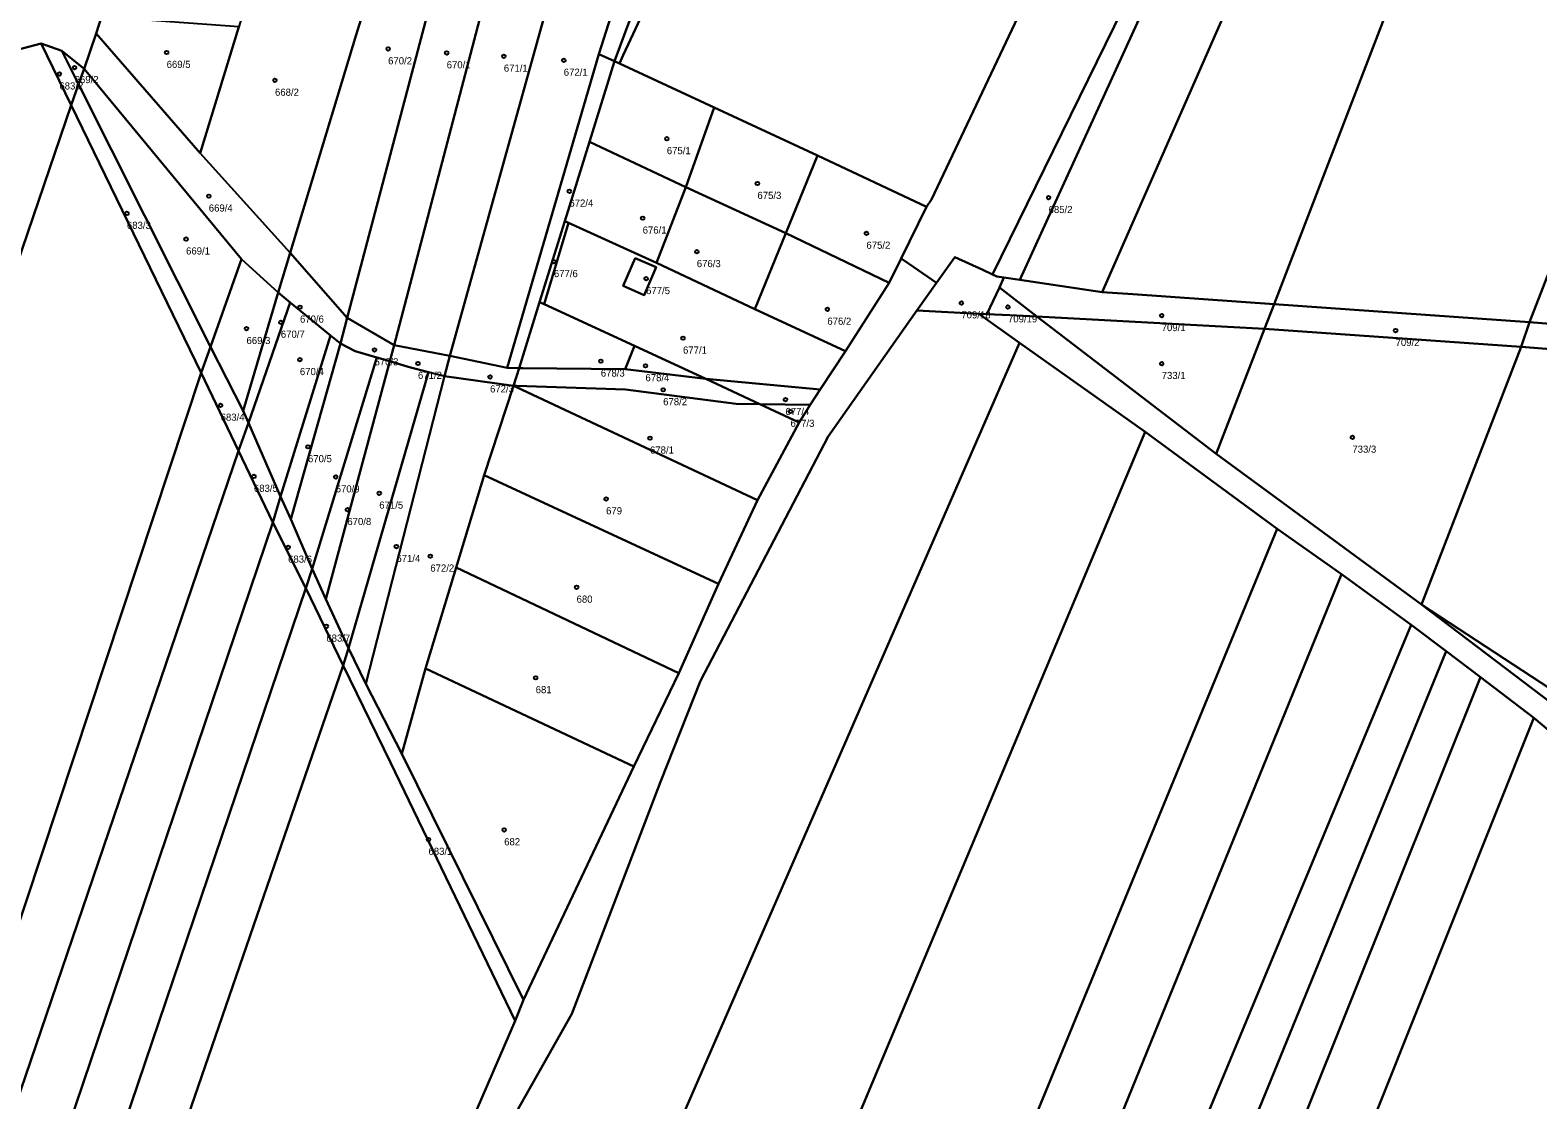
# Model space of a CAD drawing. Extents: x -587171 to -555306, y -1167727 to -1074732.
# Drawn here: x -585851.6 to -585640.5, y -1166041.5 to -1165891.7 of the extents above; entities that cross this region are included whole.
import ezdxf

# ---------------------------------------------------------------- set-up
doc = ezdxf.new("R2010")
doc.units = 0
doc.layers.add('Definiční body', color=7, linetype='Continuous')
doc.layers.add('Polygon parcely', color=7, linetype='Continuous')

msp = doc.modelspace()

# ---------------------------------------------------------------- linework, layer by layer
at = {"layer": 'Definiční body'}
for centre in [(-585832.47, -1165894.79), (-585801.46, -1165894.29), (-585793.26, -1165894.85), (-585845.35, -1165896.92), (-585785.26, -1165895.32), (-585776.87, -1165895.89), (-585847.49, -1165897.81), (-585817.3, -1165898.69), (-585762.44, -1165906.87), (-585776.08, -1165914.22), (-585749.75, -1165913.14), (-585826.57, -1165914.91), (-585708.98, -1165915.12), (-585838.03, -1165917.33), (-585765.82, -1165917.99), (-585734.49, -1165920.12), (-585829.75, -1165920.92), (-585758.24, -1165922.69), (-585778.25, -1165924.09), (-585765.34, -1165926.47), (-585813.8, -1165930.46), (-585739.96, -1165930.76), (-585721.2, -1165929.87), (-585714.67, -1165930.43), (-585816.48, -1165932.58), (-585693.15, -1165931.65), (-585821.29, -1165933.46), (-585760.17, -1165934.8), (-585660.4, -1165933.73), (-585803.37, -1165936.45), (-585813.81, -1165937.81), (-585797.28, -1165938.34), (-585771.68, -1165938.02), (-585765.43, -1165938.67), (-585693.15, -1165938.36), (-585787.19, -1165940.24), (-585762.95, -1165942.03), (-585745.83, -1165943.4), (-585824.91, -1165944.2), (-585745.12, -1165945.06), (-585812.68, -1165950.01), (-585764.79, -1165948.8), (-585666.45, -1165948.68), (-585820.25, -1165954.16), (-585808.8, -1165954.24), (-585802.7, -1165956.51), (-585770.94, -1165957.31), (-585807.17, -1165958.81), (-585815.46, -1165964.08), (-585800.3, -1165963.98), (-585795.55, -1165965.33), (-585775.07, -1165969.68), (-585810.11, -1165975.14), (-585780.8, -1165982.36), (-585795.81, -1166005), (-585785.21, -1166003.66)]:
    msp.add_circle(centre, 0.25, dxfattribs=at)
at = {"layer": 'Polygon parcely'}
for points in [[(-585870.27, -1165898.87), (-585850.05, -1165893.53), (-585847.15, -1165894.58), (-585844.03, -1165897.09), (-585842.32, -1165892.13), (-585841.6, -1165889.8), (-585841.17, -1165888.52), (-585815.11, -1165874.74), (-585795.32, -1165860.24), (-585754.28, -1165848.65), (-585716.17, -1165840.28), (-585686.38, -1165834.81), (-585673.05, -1165836.56), (-585671.95, -1165836.7), (-585661.69, -1165837.97), (-585655.79, -1165834.03), (-585634.24, -1165832.33), (-585601.64, -1165829.48), (-585574.23, -1165827.48), (-585571.06, -1165827.26), (-585554.63, -1165826.13), (-585538.56, -1165825.04), (-585509.22, -1165823.03)], [(-585857.09, -1166132.81), (-585800.5, -1166064.62), (-585786.16, -1166047.86), (-585775.72, -1166029.42), (-585763.32, -1165996.92), (-585757.73, -1165982.77), (-585739.86, -1165948.58), (-585727.42, -1165930.93), (-585724.68, -1165927.05), (-585727.83, -1165924.86), (-585729.61, -1165923.62), (-585731.3, -1165927.07), (-585737.4, -1165936.62), (-585740.97, -1165941.97), (-585742.35, -1165944.15), (-585743.89, -1165946.59), (-585749.74, -1165957.49), (-585755.19, -1165969.19), (-585760.76, -1165981.69), (-585767.07, -1165994.78), (-585782.52, -1166027.47), (-585783.68, -1166030.4), (-585789.78, -1166044.54), (-585858.06, -1166126.6)], [(-585639.27, -1166061.26), (-585624.81, -1166011.66), (-585622.9, -1165997.8), (-585656.76, -1165972.11), (-585685.5, -1165950.98), (-585710.63, -1165931.78), (-585714.42, -1165931.59), (-585717.62, -1165931.43), (-585718.77, -1165931.37), (-585713.04, -1165935.44), (-585695.44, -1165947.93), (-585676.97, -1165961.48), (-585667.98, -1165967.84), (-585658.24, -1165974.94), (-585653.3, -1165978.63), (-585648.49, -1165982.29), (-585641.06, -1165987.95), (-585633.7, -1165994.13), (-585628.54, -1165999.45), (-585627.74, -1166007.71), (-585629.41, -1166018.09), (-585639.38, -1166050.43)], [(-585517, -1166077.05), (-585541.09, -1166058.04), (-585565.07, -1166039.39), (-585585.24, -1166022.98), (-585606.74, -1166006.31), (-585619.63, -1165996.62), (-585633.67, -1165987.2), (-585656.76, -1165972.11), (-585622.9, -1165997.8), (-585591.19, -1166022.61), (-585558.35, -1166048.55), (-585539.18, -1166063.54), (-585526.26, -1166073.82), (-585481.14, -1166108.66)]]:
    msp.add_lwpolyline(points, dxfattribs=at)
for points in [[(-585571.06, -1165827.26), (-585574.23, -1165827.48), (-585601.64, -1165829.48), (-585641.63, -1165932.57), (-585613.18, -1165934.86)], [(-585601.64, -1165829.48), (-585634.24, -1165832.33), (-585641.27, -1165836.1), (-585677.41, -1165930.03), (-585641.63, -1165932.57)], [(-585716.83, -1165925.87), (-585673.05, -1165836.56), (-585686.38, -1165834.81), (-585691.18, -1165843.07), (-585725.39, -1165915.36), (-585726.06, -1165916.4), (-585729.61, -1165923.62), (-585727.83, -1165924.86), (-585724.68, -1165927.05), (-585722.13, -1165923.43), (-585718.21, -1165925.23)], [(-585671.95, -1165836.7), (-585673.05, -1165836.56), (-585716.83, -1165925.87), (-585716.21, -1165926.15), (-585715.23, -1165926.3), (-585713.03, -1165926.63)], [(-585713.03, -1165926.63), (-585701.5, -1165928.37), (-585667.19, -1165850.25), (-585671.06, -1165850.48), (-585677.87, -1165854.93), (-585670.92, -1165845.89), (-585661.69, -1165837.97), (-585671.95, -1165836.7)], [(-585697.2, -1165928.65), (-585677.41, -1165930.03), (-585641.27, -1165836.1), (-585644.54, -1165837.77), (-585658.98, -1165849.16), (-585667.19, -1165850.25), (-585701.5, -1165928.37)], [(-585725.39, -1165915.36), (-585691.18, -1165843.07), (-585696.32, -1165840.59), (-585718.16, -1165845.26), (-585748.18, -1165851.68), (-585750.24, -1165856.07), (-585752.66, -1165861.23), (-585768.55, -1165895.15), (-585769.07, -1165896.34), (-585755.79, -1165902.5), (-585741.34, -1165909.22), (-585726.06, -1165916.4)], [(-585718.16, -1165845.26), (-585718, -1165843.31), (-585753.12, -1165851.14), (-585769.78, -1165896.02), (-585769.07, -1165896.34), (-585768.55, -1165895.15), (-585752.66, -1165861.23), (-585750.24, -1165856.07), (-585748.18, -1165851.68)], [(-585792.84, -1165937.27), (-585784.8, -1165938.96), (-585771.98, -1165895.04), (-585758.41, -1165852.51), (-585770.29, -1165856.2)], [(-585755.86, -1165851.89), (-585758.41, -1165852.51), (-585771.98, -1165895.04), (-585769.78, -1165896.02), (-585753.12, -1165851.14)], [(-585770.29, -1165856.2), (-585780.43, -1165858.83), (-585800.62, -1165935.76), (-585792.84, -1165937.27)], [(-585780.43, -1165858.83), (-585788.5, -1165861.07), (-585807.21, -1165931.95), (-585800.62, -1165935.76)], [(-585793.94, -1165863.28), (-585797.31, -1165864.54), (-585805.95, -1165892.32), (-585815.17, -1165922.86), (-585807.21, -1165931.95), (-585788.5, -1165861.07)], [(-585819.07, -1165880.5), (-585822.34, -1165891.19), (-585827.76, -1165908.87), (-585815.17, -1165922.86), (-585805.95, -1165892.32), (-585797.31, -1165864.54)], [(-585827.76, -1165908.87), (-585822.34, -1165891.19), (-585841.6, -1165889.8), (-585842.32, -1165892.13)], [(-585815.17, -1165922.86), (-585827.76, -1165908.87), (-585842.32, -1165892.13), (-585844.03, -1165897.09), (-585822, -1165923.75), (-585816.85, -1165928.41)], [(-585904.52, -1166074.48), (-585845.85, -1165902.18), (-585850.05, -1165893.53), (-585870.27, -1165898.87), (-585932.21, -1166073.21), (-585988.94, -1166238.56), (-585965.05, -1166254.11)], [(-585845.85, -1165902.18), (-585844.8, -1165899.24), (-585847.15, -1165894.58), (-585850.05, -1165893.53)], [(-585847.15, -1165894.58), (-585844.8, -1165899.24), (-585844.03, -1165897.09)], [(-585844.03, -1165897.09), (-585844.8, -1165899.24), (-585826.33, -1165936.01), (-585822, -1165923.75)], [(-585773.28, -1165907.29), (-585769.78, -1165896.02), (-585771.98, -1165895.04), (-585784.8, -1165938.96), (-585783.12, -1165939.01), (-585780.25, -1165929.76), (-585776.73, -1165918.41)], [(-585772.49, -1165907.66), (-585759.76, -1165913.67), (-585755.79, -1165902.5), (-585769.07, -1165896.34), (-585769.78, -1165896.02), (-585773.28, -1165907.29)], [(-585827.65, -1165939.66), (-585826.33, -1165936.01), (-585844.8, -1165899.24), (-585845.85, -1165902.18)], [(-585867.81, -1166060.93), (-585827.65, -1165939.66), (-585845.85, -1165902.18), (-585904.52, -1166074.48), (-585965.05, -1166254.11), (-585922.99, -1166205.16), (-585914.7, -1166194.66)], [(-585759.76, -1165913.67), (-585745.79, -1165920.1), (-585741.34, -1165909.22), (-585755.79, -1165902.5)], [(-585763.87, -1165924.26), (-585759.76, -1165913.67), (-585772.49, -1165907.66), (-585773.28, -1165907.29), (-585776.73, -1165918.41), (-585776.2, -1165918.65)], [(-585745.79, -1165920.1), (-585731.3, -1165927.07), (-585729.61, -1165923.62), (-585726.06, -1165916.4), (-585741.34, -1165909.22)], [(-585763.87, -1165924.26), (-585750.1, -1165930.74), (-585745.79, -1165920.1), (-585759.76, -1165913.67)], [(-585780.25, -1165929.76), (-585779.61, -1165930.05), (-585776.2, -1165918.65), (-585776.73, -1165918.41)], [(-585776.2, -1165918.65), (-585779.61, -1165930.05), (-585766.96, -1165935.87), (-585756.98, -1165940.51), (-585740.97, -1165941.97), (-585737.4, -1165936.62), (-585750.1, -1165930.74), (-585763.87, -1165924.26)], [(-585750.1, -1165930.74), (-585737.4, -1165936.62), (-585731.3, -1165927.07), (-585745.79, -1165920.1)], [(-585816.85, -1165928.41), (-585822, -1165923.75), (-585826.33, -1165936.01), (-585821.77, -1165944.96)], [(-585815.18, -1165929.78), (-585809.54, -1165934.4), (-585808.13, -1165935.55), (-585807.21, -1165931.95), (-585815.17, -1165922.86), (-585816.85, -1165928.41)], [(-585766.86, -1165923.59), (-585763.92, -1165924.86), (-585765.6, -1165928.77), (-585768.55, -1165927.47)], [(-585766.86, -1165923.59), (-585768.55, -1165927.47), (-585765.6, -1165928.77), (-585763.92, -1165924.86)], [(-585715.23, -1165926.3), (-585716.21, -1165926.15), (-585716.83, -1165925.87), (-585718.21, -1165925.23), (-585722.13, -1165923.43), (-585724.68, -1165927.05), (-585727.42, -1165930.93), (-585718.77, -1165931.37), (-585717.62, -1165931.43), (-585715.88, -1165927.69)], [(-585710.63, -1165931.78), (-585678.76, -1165933.49), (-585677.41, -1165930.03), (-585697.2, -1165928.65), (-585701.5, -1165928.37), (-585713.03, -1165926.63), (-585715.23, -1165926.3), (-585715.88, -1165927.69)], [(-585821.77, -1165944.96), (-585821.03, -1165946.66), (-585815.18, -1165929.78), (-585816.85, -1165928.41)], [(-585717.62, -1165931.43), (-585714.42, -1165931.59), (-585710.63, -1165931.78), (-585715.88, -1165927.69)], [(-585821.03, -1165946.66), (-585816.54, -1165956.95), (-585809.54, -1165934.4), (-585815.18, -1165929.78)], [(-585779.61, -1165930.05), (-585780.25, -1165929.76), (-585783.12, -1165939.01), (-585782.6, -1165939.01), (-585768.27, -1165939.12), (-585766.96, -1165935.87)], [(-585642.8, -1165936.02), (-585641.63, -1165932.57), (-585677.41, -1165930.03), (-585678.76, -1165933.49)], [(-585864.03, -1166227.56), (-585860.12, -1166228.08), (-585843.44, -1166230.06), (-585839.63, -1166231.59), (-585791.33, -1166115.09), (-585713.04, -1165935.44), (-585718.77, -1165931.37), (-585727.42, -1165930.93), (-585739.86, -1165948.58), (-585757.73, -1165982.77), (-585763.32, -1165996.92), (-585775.72, -1166029.42), (-585786.16, -1166047.86), (-585800.5, -1166064.62), (-585863.23, -1166225.45)], [(-585801.23, -1165938.04), (-585800.62, -1165935.76), (-585807.21, -1165931.95), (-585808.13, -1165935.55), (-585806.09, -1165936.62), (-585803.05, -1165937.51)], [(-585685.5, -1165950.98), (-585678.76, -1165933.49), (-585710.63, -1165931.78)], [(-585614.51, -1165938.25), (-585613.18, -1165934.86), (-585641.63, -1165932.57), (-585642.8, -1165936.02)], [(-585816.54, -1165956.95), (-585815.1, -1165960.16), (-585808.13, -1165935.55), (-585809.54, -1165934.4)], [(-585656.76, -1165972.11), (-585642.8, -1165936.02), (-585678.76, -1165933.49), (-585685.5, -1165950.98)], [(-585829.45, -1166269.74), (-585764.55, -1166112.76), (-585695.44, -1165947.93), (-585713.04, -1165935.44), (-585791.33, -1166115.09), (-585839.63, -1166231.59), (-585831.6, -1166234.8), (-585824.68, -1166243.17), (-585825.58, -1166255.62), (-585831.15, -1166268.8)], [(-585822.39, -1165950.58), (-585821.03, -1165946.66), (-585821.77, -1165944.96), (-585826.33, -1165936.01), (-585827.65, -1165939.66)], [(-585815.1, -1165960.16), (-585812.1, -1165967.12), (-585803.05, -1165937.51), (-585806.09, -1165936.62), (-585808.13, -1165935.55)], [(-585793.57, -1165940.12), (-585792.84, -1165937.27), (-585800.62, -1165935.76), (-585801.23, -1165938.04), (-585798.64, -1165938.8), (-585795.79, -1165939.54)], [(-585768.27, -1165939.12), (-585756.98, -1165940.51), (-585766.96, -1165935.87)], [(-585614.51, -1165938.25), (-585642.8, -1165936.02), (-585656.76, -1165972.11), (-585633.67, -1165987.2)], [(-585812.1, -1165967.12), (-585810.18, -1165971.37), (-585801.23, -1165938.04), (-585803.05, -1165937.51)], [(-585810.18, -1165971.37), (-585806.99, -1165978.19), (-585795.79, -1165939.54), (-585798.64, -1165938.8), (-585801.23, -1165938.04)], [(-585784.8, -1165938.96), (-585792.84, -1165937.27), (-585793.57, -1165940.12), (-585783.91, -1165941.47), (-585783.12, -1165939.01)], [(-585749.4, -1165944.03), (-585756.98, -1165940.51), (-585768.27, -1165939.12), (-585782.6, -1165939.01), (-585783.12, -1165939.01), (-585783.91, -1165941.47), (-585783.42, -1165941.49), (-585768.22, -1165941.97), (-585752.72, -1165943.97)], [(-585860.26, -1166061.57), (-585822.39, -1165950.58), (-585827.65, -1165939.66), (-585867.81, -1166060.93), (-585914.7, -1166194.66), (-585901.49, -1166178.97)], [(-585806.99, -1165978.19), (-585804.6, -1165983.2), (-585793.57, -1165940.12), (-585795.79, -1165939.54)], [(-585804.6, -1165983.2), (-585799.55, -1165993.01), (-585796.22, -1165981.04), (-585791.92, -1165966.9), (-585787.99, -1165953.97), (-585783.91, -1165941.47), (-585793.57, -1165940.12)], [(-585787.99, -1165953.97), (-585755.19, -1165969.19), (-585749.74, -1165957.49), (-585783.48, -1165941.66), (-585783.91, -1165941.47)], [(-585749.4, -1165944.03), (-585752.72, -1165943.97), (-585768.22, -1165941.97), (-585783.42, -1165941.49), (-585783.91, -1165941.47), (-585783.48, -1165941.66), (-585749.74, -1165957.49), (-585743.89, -1165946.59)], [(-585740.97, -1165941.97), (-585756.98, -1165940.51), (-585749.4, -1165944.03), (-585742.35, -1165944.15)], [(-585742.35, -1165944.15), (-585749.4, -1165944.03), (-585743.89, -1165946.59)], [(-585817.61, -1165960.59), (-585816.54, -1165956.95), (-585821.03, -1165946.66), (-585822.39, -1165950.58)], [(-585788.55, -1166232.18), (-585743.05, -1166122.17), (-585676.97, -1165961.48), (-585695.44, -1165947.93), (-585764.55, -1166112.76), (-585829.45, -1166269.74), (-585854.01, -1166327.27), (-585833.65, -1166341.21)], [(-585847.32, -1166048.49), (-585817.61, -1165960.59), (-585822.39, -1165950.58), (-585860.26, -1166061.57), (-585901.49, -1166178.97), (-585887.24, -1166161.79)], [(-585791.92, -1165966.9), (-585760.76, -1165981.69), (-585755.19, -1165969.19), (-585787.99, -1165953.97)], [(-585812.97, -1165969.82), (-585812.1, -1165967.12), (-585815.1, -1165960.16), (-585816.54, -1165956.95), (-585817.61, -1165960.59)], [(-585871.75, -1166143.2), (-585812.97, -1165969.82), (-585817.61, -1165960.59), (-585847.32, -1166048.49), (-585887.24, -1166161.79)], [(-585785.35, -1166254.74), (-585746.19, -1166159.95), (-585707.22, -1166064.23), (-585667.98, -1165967.84), (-585676.97, -1165961.48), (-585743.05, -1166122.17), (-585788.55, -1166232.18), (-585833.65, -1166341.21), (-585823.84, -1166347.93)], [(-585813.81, -1166354.8), (-585767.77, -1166243.17), (-585718.04, -1166118.8), (-585658.24, -1165974.94), (-585667.98, -1165967.84), (-585707.22, -1166064.23), (-585746.19, -1166159.95), (-585785.35, -1166254.74), (-585823.84, -1166347.93)], [(-585807.75, -1165980.66), (-585806.99, -1165978.19), (-585810.18, -1165971.37), (-585812.1, -1165967.12), (-585812.97, -1165969.82)], [(-585796.22, -1165981.04), (-585767.07, -1165994.78), (-585760.76, -1165981.69), (-585791.92, -1165966.9)], [(-585807.75, -1165980.66), (-585812.97, -1165969.82), (-585871.75, -1166143.2), (-585858.06, -1166126.6)], [(-585653.3, -1165978.63), (-585658.24, -1165974.94), (-585718.04, -1166118.8), (-585767.77, -1166243.17), (-585761.18, -1166246.21), (-585710.18, -1166117.72)], [(-585801.12, -1165994.23), (-585783.68, -1166030.4), (-585782.52, -1166027.47), (-585799.55, -1165993.01), (-585804.6, -1165983.2), (-585806.99, -1165978.19), (-585807.75, -1165980.66)], [(-585754.6, -1166249.06), (-585703.81, -1166120.35), (-585648.49, -1165982.29), (-585653.3, -1165978.63), (-585710.18, -1166117.72), (-585761.18, -1166246.21)], [(-585858.06, -1166126.6), (-585789.78, -1166044.54), (-585783.68, -1166030.4), (-585801.12, -1165994.23), (-585807.75, -1165980.66)], [(-585782.52, -1166027.47), (-585767.07, -1165994.78), (-585796.22, -1165981.04), (-585799.55, -1165993.01)], [(-585801.17, -1166363.45), (-585792.93, -1166369.09), (-585746.15, -1166252.04), (-585695.64, -1166124.76), (-585641.06, -1165987.95), (-585648.49, -1165982.29), (-585703.81, -1166120.35), (-585754.6, -1166249.06)], [(-585697.57, -1166186.15), (-585685.24, -1166163.9), (-585672.28, -1166135.9), (-585658.71, -1166106.18), (-585639.38, -1166050.43), (-585629.41, -1166018.09), (-585627.74, -1166007.71), (-585628.54, -1165999.45), (-585633.7, -1165994.13), (-585641.06, -1165987.95), (-585695.64, -1166124.76), (-585746.15, -1166252.04), (-585792.93, -1166369.09), (-585785.16, -1166374.4), (-585771.47, -1166387.86), (-585760.73, -1166347.69), (-585753.1, -1166320.6), (-585744.73, -1166294.85), (-585715.71, -1166223.84)]]:
    msp.add_lwpolyline(points, close=True, dxfattribs=at)

# ---------------------------------------------------------------- texts
at = {"layer": 'Definiční body'}
for s, p in [('669/5', (-585832.47, -1165896.95)), ('670/2', (-585801.46, -1165896.45)), ('670/1', (-585793.26, -1165897.01)), ('671/1', (-585785.26, -1165897.48)), ('672/1', (-585776.87, -1165898.05)), ('683/2', (-585847.49, -1165899.97)), ('669/2', (-585845.35, -1165899.08)), ('668/2', (-585817.3, -1165900.85)), ('675/1', (-585762.44, -1165909.03)), ('669/4', (-585826.57, -1165917.07)), ('672/4', (-585776.08, -1165916.38)), ('675/3', (-585749.75, -1165915.3)), ('685/2', (-585708.98, -1165917.28)), ('683/3', (-585838.03, -1165919.49)), ('676/1', (-585765.82, -1165920.15)), ('669/1', (-585829.75, -1165923.08)), ('675/2', (-585734.49, -1165922.28)), ('676/3', (-585758.24, -1165924.85)), ('677/6', (-585778.25, -1165926.25)), ('677/5', (-585765.34, -1165928.63)), ('670/6', (-585813.8, -1165932.62)), ('676/2', (-585739.96, -1165932.92)), ('709/18', (-585721.2, -1165932.03)), ('709/19', (-585714.67, -1165932.59)), ('709/1', (-585693.15, -1165933.81)), ('669/3', (-585821.29, -1165935.62)), ('670/7', (-585816.48, -1165934.74)), ('709/2', (-585660.4, -1165935.89)), ('677/1', (-585760.17, -1165936.96)), ('670/4', (-585813.81, -1165939.97)), ('670/3', (-585803.37, -1165938.61)), ('678/3', (-585771.68, -1165940.18)), ('671/2', (-585797.28, -1165940.5)), ('672/3', (-585787.19, -1165942.4)), ('678/4', (-585765.43, -1165940.83)), ('733/1', (-585693.15, -1165940.52)), ('678/2', (-585762.95, -1165944.19)), ('683/4', (-585824.91, -1165946.36)), ('677/4', (-585745.83, -1165945.56)), ('677/3', (-585745.12, -1165947.22)), ('678/1', (-585764.79, -1165950.96)), ('733/3', (-585666.45, -1165950.84)), ('670/5', (-585812.68, -1165952.17)), ('683/5', (-585820.25, -1165956.32)), ('670/9', (-585808.8, -1165956.4)), ('671/5', (-585802.7, -1165958.67)), ('670/8', (-585807.17, -1165960.97)), ('679', (-585770.94, -1165959.47)), ('683/6', (-585815.46, -1165966.24)), ('671/4', (-585800.3, -1165966.14)), ('672/2', (-585795.55, -1165967.49)), ('680', (-585775.07, -1165971.84)), ('683/7', (-585810.11, -1165977.3)), ('681', (-585780.8, -1165984.52)), ('682', (-585785.21, -1166005.82)), ('683/1', (-585795.81, -1166007.16))]:
    msp.add_text(s, height=1, dxfattribs=at).set_placement(p)

doc.saveas('drawing.dxf')
